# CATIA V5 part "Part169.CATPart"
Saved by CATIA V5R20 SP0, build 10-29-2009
Part number: IA 6717SF
Revision: ANY
Definition: UNKNOWN
Nomenclature: IA 6717SF
Source: Unknown
Bounding box of the stored display mesh (mm): x -3.35 to 3.35, y -7.95 to 9.02, z -3.186 to 3.186
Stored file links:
  C:\Users\Utente\Desktop\IO LAVORO\3D X SITO CF\CUMSA\3D files FA\FA 126700\Part169.CATPart
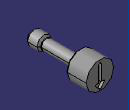
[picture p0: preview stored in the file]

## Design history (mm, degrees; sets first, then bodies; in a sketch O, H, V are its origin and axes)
Body1 "Cortar-Extruir2" (main body)
  Solid1: solid without history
